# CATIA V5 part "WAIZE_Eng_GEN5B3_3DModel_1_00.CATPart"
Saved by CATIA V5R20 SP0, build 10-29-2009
Part number: GEN5B3 3D Modell V1
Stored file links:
  O:\Backup - WAIZE Prototyping Server\Projekte\Projekt ATLAS GEN5\GEN5B3 3D Modell V1.CATPart

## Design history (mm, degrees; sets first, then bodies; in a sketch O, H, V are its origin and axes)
Set1
  Point1 "Point.1": stored without definition
  Line1 "Line.1": stored without definition
  Line2 "Line.2": stored without definition
  Line3 "Line.3": stored without definition
  Line4 "Line.4": stored without definition
  Line5 "Line.5": stored without definition
  Line6 "Line.6": stored without definition
  Line7 "Line.7": stored without definition
  Line8 "Line.8": stored without definition
  DatumCurve1 "Curve.1"
  DatumCurve2 "Curve.2"
  Point2 "Point.2": stored without definition
  Line9 "Line.9": stored without definition
  Line10 "Line.10": stored without definition
  Line11 "Line.11": stored without definition
  Line12 "Line.12": stored without definition
  Line13 "Line.13": stored without definition
  Line14 "Line.14": stored without definition
  Line15 "Line.15": stored without definition
  Line16 "Line.16": stored without definition
Body1 "Volumenkörper1" (main body)
  Solid1: solid without history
